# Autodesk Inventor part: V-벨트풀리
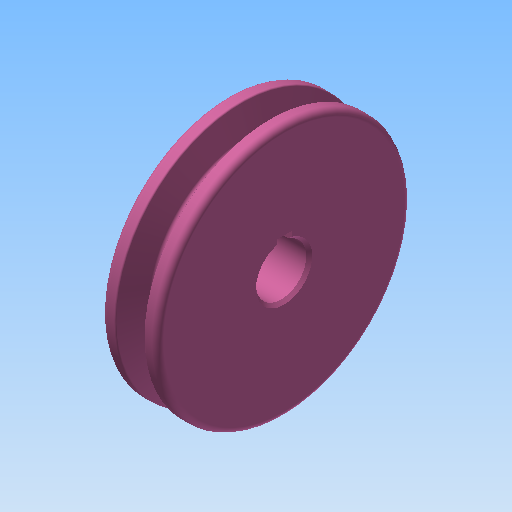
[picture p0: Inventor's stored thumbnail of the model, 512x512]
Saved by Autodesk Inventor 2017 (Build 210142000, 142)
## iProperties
Created: 2018-11
Part Number: V-벨트풀리
Material: 알루미늄 6061
Document SubType Name: Modeling
Designer: mduedu
Density: 1 g/cm^3
Appearance: Pink
Author: mduedu
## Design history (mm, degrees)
sketch "스케치1"
  geometry: L1 (-9.5, 0)-(9.5, 0); L2 (9.5, 0)-(9.5, 42.7); L3 (9.5, 42.7)-(-9.5, 42.7); L4 (-9.5, 42.7)-(-9.5, 0); L5 (-4.877, 42.7)-(-1.953, 33.7); L6 (-1.953, 33.7)-(1.953, 33.7); L7 (1.953, 33.7)-(4.877, 42.7); L8 (0, 0)-(0, 42.7); L9 (-9.5, 40)-(9.5, 40); 3 further points
  constraints: 18 end point, 8 point on line, 3 perpendicular, 2 midpoint, 2 parallel, 1 coincident, 1 horizontal, 1 other
  dimensions: "d0" = 85.4 diameter of L3 L1; "d2" = 19 distance of L2.end L3.end; "d3" = 80 diameter of L9 L1; "d4" = 36 deg angle of L7 L5; "d5" = 6.3 distance between parallel lines of L6 L9; "d6" = 8 distance of point (4, 40) point (-4, 40)
revolve "회전1" sketch "스케치1" stored, may be unused: angle "d7" = 90 deg
sketch "스케치2"
  geometry: L1 (-2.5, 8.124)-(2.5, 8.124); L2 (2.5, 8.124)-(2.5, 10.8); L3 (2.5, 10.8)-(-2.5, 10.8); L4 (-2.5, 10.8)-(-2.5, 8.124); A1 r 8.5 centre (0, 0) between (-2.5, 8.124) and (2.5, 8.124); 1 further point
  constraints: 8 end point, 2 parallel, 2 point on circle, 1 centre point, 1 coincident, 1 horizontal, 1 perpendicular
  dimensions: "d8" = 17 diameter of A1; "d10" = 19.3 dimension on A1 L3; "d11" = 5 distance of L2.end L3.end
extrude "돌출1" cut sketch "스케치2" stored distance "d12" = 10; taper "d13" = 0 deg
chamfer "모따기1" distance "d14" = 1; stored, may be unused: second distance "d15" = 2, angle "d16" = 45 deg
fillet "모깎기1" dims "d17" = 1, "d18" = 0.5, "d19" = 2
sketch "스케치3"
  geometry: C1 r 17.5 at (0, 0); C2 r 28.5 at (0, 0); 1 further point
  constraints: 2 centre point, 2 coincident
  dimensions: "d20" = 35 diameter of C1; "d23" = 57 diameter of C2
extrude "돌출2" cut sketch "스케치3" distance "d24" = 9.5; taper "d25" = 0 deg
fillet "모깎기2" dims "d26" = 3
node "솔리드1"
